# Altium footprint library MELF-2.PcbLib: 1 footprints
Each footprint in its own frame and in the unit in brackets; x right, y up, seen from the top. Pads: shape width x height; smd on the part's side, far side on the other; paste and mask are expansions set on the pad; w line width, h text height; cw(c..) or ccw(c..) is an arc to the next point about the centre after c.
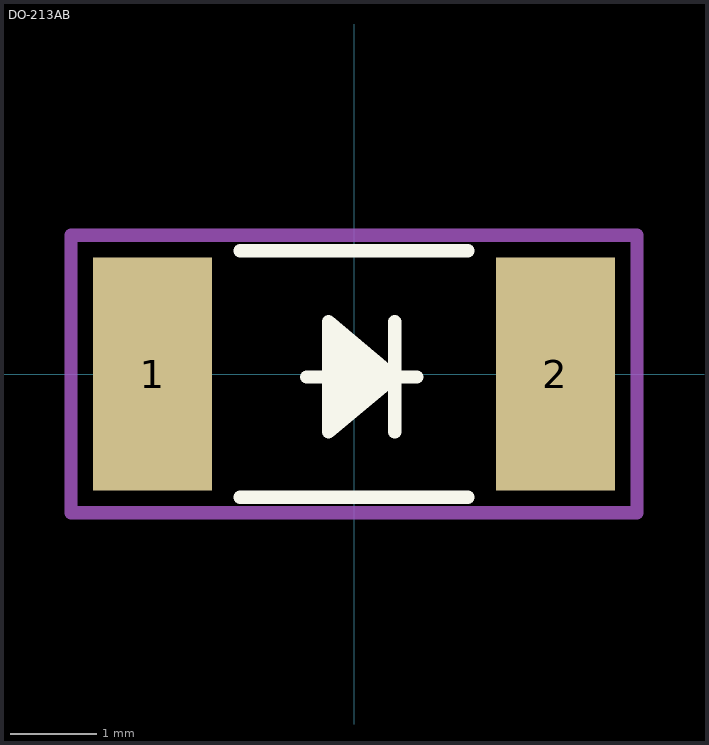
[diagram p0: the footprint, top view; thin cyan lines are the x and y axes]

## DO-213AB [mil]
pads (2):
  rect 54x106 smd: 1(-91.5,0) 2(91.5,0)
Top Overlay:
  lines w6: -51.75,-56 51.75,-56 ; -51.75,56 51.75,56 ; -21.52,-1.31 28.48,-1.31 ; -11.52,-21.31 18.48,-1.31 ; -11.52,-16.31 18.48,-1.31 ; -11.52,-11.31 18.48,-1.31 ; -11.52,-6.31 18.48,-1.31 ; -11.52,3.69 18.48,-1.31 ; -11.52,8.69 18.48,-1.31 ; -11.52,13.69 18.48,-1.31 ; -11.52,18.69 18.48,-1.31 ; 18.48,-26.31 18.48,23.69 ; 18.48,-1.31 -11.52,23.69 -11.52,-26.31 18.48,-1.31
Mechanical 15:
  lines w6: -128.5,-63 -128.5,63 128.5,63 128.5,-63 -128.5,-63
3D body "User Library-MELF DO213AB.step": height 101.99, standoff 0.37, extent -93.32,-50.63 95.66,51.73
